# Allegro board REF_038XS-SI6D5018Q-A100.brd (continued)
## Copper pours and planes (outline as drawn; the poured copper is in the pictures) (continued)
UDBGND on L05_DPS: 1.02,1.02 1.02,135.8 4.66,139.45 78,139.45 83.79,133.65 83.79,126.57 85.32,125.04 124.18,125.04 126.36,127.23 126.36,135.33 130.48,139.45 171.58,139.45 172.4,138.62 172.4,130.37 170.94,128.91 149.12,128.91 136.09,115.87 80.57,115.87 67.54,128.91 22.61,128.91 16.76,123.06 16.76,104.9 11.18,99.31 11.18,22.86 12.83,21.21 560.7,21.21 570.48,30.99 570.48,100.58 564.51,106.55 564.51,114.58 559.18,119.91 411.58,119.91 408.69,122.81 408.69,133.6 410.46,135.38 450.39,135.38 460.53,125.25 489.66,125.25 492.38,127.97 492.38,132.26 495.5,135.38 556.01,135.38 564.13,143.51 564.13,280.54 559.82,284.86 422.4,284.86 421.13,286.13 421.13,293.75 422.15,294.77 433.96,294.77 439.29,300.1 559.69,300.1 565.02,305.44 565.02,324.74 570.36,330.07 570.36,406.27 569.09,407.54 83.82,407.54 83.69,407.67 12.7,407.67 10.92,405.89 10.92,330.07 32.26,308.74 157.65,308.74 159.89,306.49 159.89,288.42 158.24,286.77 151.89,286.77 139.06,299.59 112.14,299.59 99.31,286.77 5.65,286.77 1.02,291.4 1.02,428.24 580.64,428.24 580.64,1.02
UT1_UP5V on BOTTOM: 81.43,274.88 81.43,274.65 81.53,274.55 84.02,274.55 84.12,274.65 84.12,275.13 84,275.26 82.33,275.26 82,274.93 81.48,274.93
UT1_UP5V on BOTTOM: 222.81,207.75 222.81,209.44 222.71,209.54 221.46,209.54 221.01,209.09 221.01,208.61 220.8,208.4 219.68,208.4 219.38,208.1 218.74,208.1 218.62,207.97 218.62,204.57 218.72,204.46 220.32,204.46 220.75,204.9 220.75,206.62 221.44,207.31 222.37,207.31
UT1_UP5V on BOTTOM: 342.81,207.75 342.81,209.44 342.71,209.54 341.46,209.54 341.01,209.09 341.01,208.61 340.8,208.4 339.68,208.4 339.38,208.1 338.74,208.1 338.62,207.97 338.62,204.57 338.72,204.46 340.32,204.46 340.75,204.9 340.75,206.62 341.44,207.31 342.37,207.31
UT1_UP5V on BOTTOM: 501.27,222.42 501.27,222.19 501.37,222.09 503.86,222.09 503.96,222.19 503.96,222.67 503.83,222.8 502.16,222.8 501.83,222.47 501.32,222.47
UT1_UP5V on BOTTOM: 475.56,131.88 475.56,134.04 475.18,134.42 469.47,134.42 469.21,134.16 469.21,131.75 469.72,131.24 470.99,131.24 471.5,131.75 475.44,131.75
UT1_UP5V on BOTTOM: 302.81,267.75 302.81,269.44 302.71,269.54 301.46,269.54 301.01,269.09 301.01,268.61 300.8,268.4 299.68,268.4 299.38,268.1 298.74,268.1 298.62,267.97 298.62,264.57 298.72,264.46 300.32,264.46 300.75,264.9 300.75,266.62 301.44,267.31 302.37,267.31
UT1_UP5V on BOTTOM: 302.81,207.75 302.81,209.44 302.71,209.54 301.46,209.54 301.01,209.09 301.01,208.61 300.8,208.4 299.68,208.4 299.38,208.1 298.74,208.1 298.62,207.97 298.62,204.57 298.72,204.46 300.32,204.46 300.75,204.9 300.75,206.62 301.44,207.31 302.37,207.31
UT1_UP5V on BOTTOM: 81.43,288.59 81.43,288.37 81.53,288.26 84.02,288.26 84.12,288.37 84.12,288.85 84,288.98 82.33,288.98 82,288.65 81.48,288.65
UT1_UP5V on BOTTOM: 81.43,261.16 81.43,260.93 81.53,260.83 84.02,260.83 84.12,260.93 84.12,261.42 84,261.54 82.33,261.54 82,261.21 81.48,261.21
UT1_UP5V on BOTTOM: 520.87,149.07 519.18,149.07 519.07,148.97 519.07,147.73 519.53,147.27 520.01,147.27 520.22,147.07 520.22,145.95 520.52,145.64 520.52,145.01 520.65,144.88 524.05,144.88 524.15,144.98 524.15,146.58 523.72,147.02 522,147.02 521.31,147.7 521.31,148.63
UT1_UP5V on BOTTOM: 109.8,195.38 109.8,197.54 109.42,197.92 103.71,197.92 103.45,197.66 103.45,195.25 103.96,194.74 105.23,194.74 105.74,195.25 109.68,195.25
UT1_UP5V on BOTTOM: 475.56,163.63 475.56,165.79 475.18,166.17 469.47,166.17 469.21,165.91 469.21,163.5 469.72,162.99 470.99,162.99 471.5,163.5 475.44,163.5
UT1_UP5V on BOTTOM: 262.81,207.75 262.81,209.44 262.71,209.54 261.46,209.54 261.01,209.09 261.01,208.61 260.8,208.4 259.68,208.4 259.38,208.1 258.74,208.1 258.62,207.97 258.62,204.57 258.72,204.46 260.32,204.46 260.75,204.9 260.75,206.62 261.44,207.31 262.37,207.31
UT1_UP5V on BOTTOM: 222.81,267.75 222.81,269.44 222.71,269.54 221.46,269.54 221.01,269.09 221.01,268.61 220.8,268.4 219.68,268.4 219.38,268.1 218.74,268.1 218.62,267.97 218.62,264.57 218.72,264.46 220.32,264.46 220.75,264.9 220.75,266.62 221.44,267.31 222.37,267.31
UT1_UP5V on BOTTOM: 109.8,227.13 109.8,229.29 109.42,229.67 103.71,229.67 103.45,229.41 103.45,227 103.96,226.49 105.23,226.49 105.74,227 109.68,227
UT1_UP5V on BOTTOM: 109.8,163.63 109.8,165.79 109.42,166.17 103.71,166.17 103.45,165.91 103.45,163.5 103.96,162.99 105.23,162.99 105.74,163.5 109.68,163.5
UT1_UP5V on BOTTOM: 475.56,195.38 475.56,197.54 475.18,197.92 469.47,197.92 469.21,197.66 469.21,195.25 469.72,194.74 470.99,194.74 471.5,195.25 475.44,195.25
UT1_UP5V on BOTTOM: 475.56,227.13 475.56,229.29 475.18,229.67 469.47,229.67 469.21,229.41 469.21,227 469.72,226.49 470.99,226.49 471.5,227 475.44,227
UT1_UP5V on BOTTOM: 501.27,204.26 501.27,204.03 501.37,203.93 503.86,203.93 503.96,204.03 503.96,204.52 503.83,204.64 502.16,204.64 501.83,204.31 501.32,204.31
UT1_UP5V on BOTTOM: 109.8,131.88 109.8,134.04 109.42,134.42 103.71,134.42 103.45,134.16 103.45,131.75 103.96,131.24 105.23,131.24 105.74,131.75 109.68,131.75
UT1_UP5V on BOTTOM: 342.81,267.75 342.81,269.44 342.71,269.54 341.46,269.54 341.01,269.09 341.01,268.61 340.8,268.4 339.68,268.4 339.38,268.1 338.74,268.1 338.62,267.97 338.62,264.57 338.72,264.46 340.32,264.46 340.75,264.9 340.75,266.62 341.44,267.31 342.37,267.31
UT1_UP5V on BOTTOM: 262.81,267.75 262.81,269.44 262.71,269.54 261.46,269.54 261.01,269.09 261.01,268.61 260.8,268.4 259.68,268.4 259.38,268.1 258.74,268.1 258.62,267.97 258.62,264.57 258.72,264.46 260.32,264.46 260.75,264.9 260.75,266.62 261.44,267.31 262.37,267.31
N16771755 on BOTTOM: 191.91,232.53 191.91,226.15 192.47,225.59 200.75,225.59 201.12,225.96 201.12,232.61 200.59,233.14 192.52,233.14
N17351004 on BOTTOM: 228.27,265.86 228.22,265.91 226.8,265.91 226.69,266.01 224.84,266.01 223.88,266.98 223.11,266.98 222.88,266.75 222.88,265.35 222.99,265.25 226.16,265.25 226.8,264.62 228.19,264.62 228.27,264.69
N18097849 on BOTTOM: 208.36,291.04 201.98,291.04 201.42,290.48 201.42,282.2 201.79,281.83 208.44,281.83 208.97,282.36 208.97,290.43
N18100716 on BOTTOM: 268.27,265.86 268.22,265.91 266.8,265.91 266.69,266.01 264.84,266.01 263.88,266.98 263.11,266.98 262.88,266.75 262.88,265.35 262.99,265.25 266.16,265.25 266.8,264.62 268.19,264.62 268.27,264.69
N18106166 on BOTTOM: 378.74,291.04 372.36,291.04 371.8,290.48 371.8,282.2 372.17,281.83 378.82,281.83 379.35,282.36 379.35,290.43
N18109033 on BOTTOM: 308.27,265.86 308.22,265.91 306.8,265.91 306.69,266.01 304.84,266.01 303.88,266.98 303.11,266.98 302.88,266.75 302.88,265.35 302.99,265.25 306.16,265.25 306.8,264.62 308.19,264.62 308.27,264.69
N18114483 on BOTTOM: 389.72,234.63 389.72,241.01 389.16,241.57 380.88,241.57 380.51,241.2 380.51,234.54 381.04,234.02 389.11,234.02
N18117350 on BOTTOM: 348.27,265.86 348.22,265.91 346.8,265.91 346.69,266.01 344.84,266.01 343.88,266.98 343.11,266.98 342.88,266.75 342.88,265.35 342.99,265.25 346.16,265.25 346.8,264.62 348.19,264.62 348.27,264.69
N18122800 on BOTTOM: 211.89,145.89 218.27,145.89 218.82,146.44 218.82,154.72 218.46,155.09 211.8,155.09 211.28,154.57 211.28,146.5
N18125667 on BOTTOM: 228.27,205.86 228.22,205.91 226.8,205.91 226.69,206.01 224.84,206.01 223.88,206.98 223.11,206.98 222.88,206.75 222.88,205.35 222.99,205.25 226.16,205.25 226.8,204.62 228.19,204.62 228.27,204.69
N18131117 on BOTTOM: 251.89,145.89 258.27,145.89 258.82,146.44 258.82,154.72 258.46,155.09 251.8,155.09 251.28,154.57 251.28,146.5
N18133984 on BOTTOM: 268.27,205.86 268.22,205.91 266.8,205.91 266.69,206.01 264.84,206.01 263.88,206.98 263.11,206.98 262.88,206.75 262.88,205.35 262.99,205.25 266.16,205.25 266.8,204.62 268.19,204.62 268.27,204.69
N18139434 on BOTTOM: 291.89,145.89 298.27,145.89 298.82,146.44 298.82,154.72 298.46,155.09 291.8,155.09 291.28,154.57 291.28,146.5
N18142301 on BOTTOM: 308.27,205.86 308.22,205.91 306.8,205.91 306.69,206.01 304.84,206.01 303.88,206.98 303.11,206.98 302.88,206.75 302.88,205.35 302.99,205.25 306.16,205.25 306.8,204.62 308.19,204.62 308.27,204.69
N18147751 on BOTTOM: 331.89,145.89 338.27,145.89 338.82,146.44 338.82,154.72 338.45,155.09 331.8,155.09 331.28,154.57 331.28,146.5
N18150618 on BOTTOM: 348.27,205.86 348.22,205.91 346.8,205.91 346.69,206.01 344.84,206.01 343.88,206.98 343.11,206.98 342.88,206.75 342.88,205.35 342.99,205.25 346.16,205.25 346.8,204.62 348.19,204.62 348.27,204.69
N22558621 on BOTTOM: 522.61,151.1 521.64,150.14 521.64,149.38 521.87,149.15 523.27,149.15 523.37,149.25 523.37,153.57 523.24,153.7 522.76,153.7 522.61,153.54

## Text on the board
Ref Des/Silkscreen Bottom: 1#A | 5#A | 4#A | 8#A | 6#A | 2#A | 7#A | 3#A | 5#D | 6#D | 5#B | 1#B | 1#D | 1#C | 5#C | 6#B | 2#B | 2#D | 2#C | 6#C | 7#B | 3#B | 3#D | 7#D | 3#C | 7#C | G6K2F-Y-5V | 8#B | 4#B | 4#D | 8#D | 4#C | 8#C
Ref Des/Silkscreen Top: 8 | 7 | 6 | UT5_SW1 | 5 | 4 | 3 | 2 | 1 | UT8_SW2 | UT5_SW2 | S1_PM_UART_TX/D11613 | S1_PM_UART_RX/D11609 | DGND | NC | S1_1SPI_CK | S1_1SPI_DI | S1_1SPI_WPZ | S1_1SPI_DO | S1_1SPI_HLD | S1_PAD_RESET | UT8_SW1 | SW10 | SW5 | JP1 | UT1_SW1 | UT1_SW2 | UT4_SW1 | UT4_SW2 | UT2_SW1 | UT2_SW2 | UT3_SW2 | UT3_SW1 | UT6_SW1 | UT7_SW2 | UT6_SW2 | UT7_SW1 | UT5_UW00 | UGND | UW00 | UT5_UW01 | UW01 | UW03 | UW02 | UT5_UW02 | PGDS | PGRD | UP5V | UW04 | UT5_UW03 | PDCS | PDCF | UW05 | URW15 | UT5_UW04 | UW07 | UW06 | URW14 | Res. | UT5_UW05 | UW08 | UW13 | UW09 | DSC | UT5_UW06 | UW12 | UW10 | UT5_UW07 | UW11 | UT8_UW15 | UT5_UW08 | UT8_UW14 | UT5_UW09 | UW14 | UT8_UW13 | URW06 | UT5_UW10 | UW15 | UT8_UW12 | URW05 | UT5_UW11 | URW04 | UT8_UW11 | UT5_UW12 | URW02 | URW03 | UT8_UW10 | UT5_UW13 | URW01 | UT8_UW09 | URW00 | UT5_UW14 | UT8_UW08 | UT5_UW15 | UT8_UW07 | UT8_UW06 | UT8_UW05 | UT8_UW04 | UT1_URW00 | UT8_UW03 | UT1_URW01 | UT8_UW02 | UT1_URW02 | UT8_UW01 | UT1_URW03 | UT8_UW00 | UT1_URW04 | UT1_URW05 | UT1_URW06 | UT1_UW07 | UT1_UW08 | UT1_UW09 | UT1_UW10 | UT1_UW11 | UT1_UW12 | UT1_UW13 | UT1_UW14 | UT1_UW15 | UT4_UW07 | UT4_URW06 | UT4_URW05 | UT4_URW04 | UT4_URW03 | UT4_URW02 | UT4_URW01 | UT4_URW00 | UT2_URW00 | UT2_URW01 | UT2_URW02 | UT2_URW03 | UT2_URW04 | UT2_URW05 | UT2_URW06 | UT2_UW07 | UT2_UW08 | UT2_UW09 | UT2_UW10 | UT2_UW11 | UT2_UW12 | UT2_UW13 | UT2_UW14 | UT2_UW15 | UT3_UW15 | UT3_UW14 | UT3_UW13 | UT3_UW12 | UT3_UW11 | UT3_UW10 | UT3_UW09 | UT3_UW08 | UT3_UW07 | UT3_URW06 | UT3_URW05 | UT3_URW04 | UT3_URW03 | UT3_URW02 | UT3_URW01 | UT3_URW00 | UT6_UW00 | UT6_UW01 | UT6_UW02 | UT6_UW03 | UT6_UW04 | UT6_UW05 | UT6_UW06 | UT6_UW07 | UT7_UW15 | UT7_UW14 | UT7_UW13 | UT6_UW08 | UT7_UW12 | UT6_UW09 | UT7_UW11 | UT6_UW10 | UT7_UW10 | UT6_UW11 | UT7_UW09 | UT6_UW12 | UT7_UW08 | UT6_UW13 | UT6_UW14 | UT7_UW07 | UT6_UW15 | UT7_UW06 | UT7_UW05 | UT7_UW04 | UT7_UW03 | UT7_UW02 | UT7_UW01 | UT7_UW00 | A1 | A | T | SSI6D50D | 16 | SITE5 | SITE1 | SITE6 | SITE2 | SITE7 | SITE3 | SITE8 | SITE4
User.10: NPTH1.62 | M3X4 | NPTH1.62X1.82 | NPTH1.72 | (0,0) | UNIT:MM | PCB Thickness:4.89
User.45: FIGURE | SIZE | 8.01 | 12.0 | 12.01 | 28.0 | 40.0 | 41.0 | 169.0 | 34.0 | 42.0 | 64.0 | 68.0 | 126.0 | 71.65x63.78 | DRILL CHART: TOP to BOTTOM | ALL UNITS ARE IN MILS | TOLERANCE | +2.0/-2.0 | +0.0/-4.0 | +3.0/-1.0 | +4.0/-0.0 | +3.0/-0.0 | +2.0/-0.0 | +3.0/-3.0 | PLATED | NON-PLATED | QTY | 5721 | 216 | 6978 | 289 | 761 | 5508 | 4 | 830 | 32 | 8
